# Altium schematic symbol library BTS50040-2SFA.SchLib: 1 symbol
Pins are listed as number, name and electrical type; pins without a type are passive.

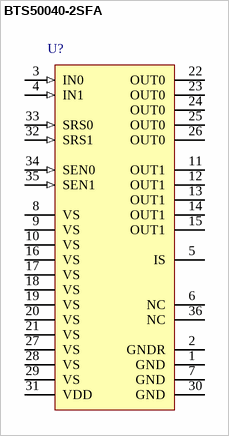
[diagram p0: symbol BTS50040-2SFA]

## BTS50040-2SFA
designator U?
Smart High-Side Power Switch, 2 Channels: 2 x 4 mOhm, 11 A Load Current, -40 to 150 degC, PG-DSO-36-44, Reel, Green; Manufacturer: Infineon; PartNumber: BTS50040-2SFA; Channels: 2; Green: TRUE; Group: Automotive Qualified; Load Current (typ): 11 A; Recommended Operating Voltage Max.: 28 V; Recommended Operating Voltage Min.: 6 V; RON @ 25degreesC: 4 mOhm; RON(max) @ 150degreesC: 8.2 mOhm; toff (max): 110 us; ton (max): 190 us
footprint INF-PG-DSO-36-44_N (SOP, 36-Leads, Body 12.7x7.5mm, Pitch 0.65mm, IPC Medium Density)
footprint INF-PG-DSO-36-44_L (SOP, 36-Leads, Body 12.7x7.5mm, Pitch 0.65mm, IPC High Density)
footprint INF-PG-DSO-36-44_M (SOP, 36-Leads, Body 12.7x7.5mm, Pitch 0.65mm, IPC Low Density)
pins: 1 GND (power) "Ground; Ground connection for control chip", 2 GNDR (power) "Ground reference; Needs to be connected to GND", 3 IN0 (in) "Input 0; activates channel 0. Has an internal pull down resistor", 4 IN1 (in) "Input 1; activates channel 1. Has an internal pull down resistor", 5 IS (hiz) "Sense Output; analog sense current signal proportional to IL0 or IL1", 6 NC "Not connected; For handling of NC pins, please see Chapter 7.1", 7 GND (power) "Ground; Ground connection for control chip", 8 VS (power) "Supply voltage; Positive power supply for power outputs", 9 VS (power) "Supply voltage; Positive power supply for power outputs", 10 VS (power) "Supply voltage; Positive power supply for power outputs", 11 OUT1 (power) "Output of channel 1; power output 1", 12 OUT1 (power) "Output of channel 1; power output 1", 13 OUT1 (power) "Output of channel 1; power output 1", 14 OUT1 (power) "Output of channel 1; power output 1", 15 OUT1 (power) "Output of channel 1; power output 1", 16 VS (power) "Supply voltage; Positive power supply for power outputs", 17 VS (power) "Supply voltage; Positive power supply for power outputs", 18 VS (power) "Supply voltage; Positive power supply for power outputs", 19 VS (power) "Supply voltage; Positive power supply for power outputs", 20 VS (power) "Supply voltage; Positive power supply for power outputs", 21 VS (power) "Supply voltage; Positive power supply for power outputs", 22 OUT0 (power) "Output of channel 0; power output 0", 23 OUT0 (power) "Output of channel 0; power output 1", 24 OUT0 (power) "Output of channel 0; power output 2", 25 OUT0 (power) "Output of channel 0; power output 3", 26 OUT0 (power) "Output of channel 0; power output 4", 27 VS (power) "Supply voltage; Positive power supply for power outputs", 28 VS (power) "Supply voltage; Positive power supply for power outputs", 29 VS (power) "Supply voltage; Positive power supply for power outputs", 30 GND (power) "Ground; Ground connection for control chip", 31 VDD (power) "Logic supply (5V)", 32 SRS1 (in) "Slew rate selector pin 0. See section "Timings" on Page 22 for seetings", 33 SRS0 (in) "Slew rate selector pin 1. See section "Timings" on Page 22 for seetings", 34 SEN0 (in) "Sense Enable for channel 0. See Table 1", 35 SEN1 (in) "Sense Enable for channel 1. See Table 2", 36 NC "Not connected; For handling of NC pins, please see Chapter 7.1"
